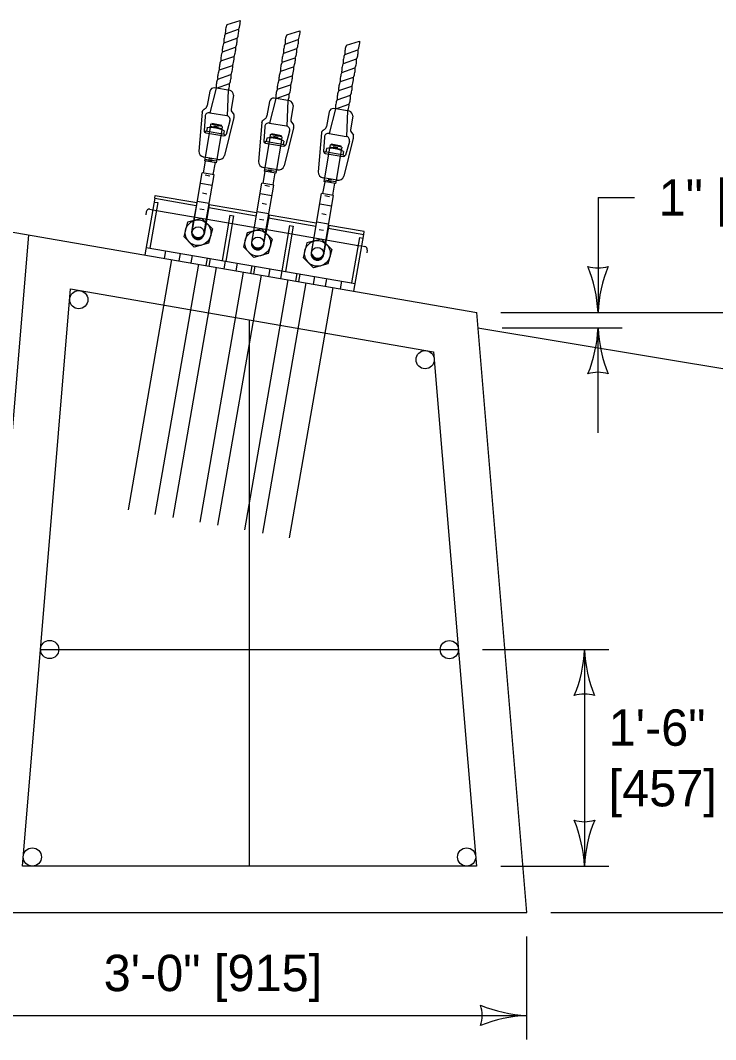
# Model space of a CAD drawing. Extents: x 49991.4 to 50021, y 49987.6 to 50011.4.
# Drawn here: x 50006.374 to 50007.521, y 49993.215 to 49994.897 of the extents above; entities that cross this region are included whole.
import ezdxf

# ---------------------------------------------------------------- set-up
doc = ezdxf.new("R2010")
doc.units = 0
for name, color, linetype in [('Level 1', 7, 'Continuous'), ('Level 2', 7, 'Continuous'), ('Level 3', 7, 'Continuous'), ('Level 4', 7, 'Continuous'), ('Level 7', 7, 'Continuous')]:
    doc.layers.add(name, color=color, linetype=linetype)

msp = doc.modelspace()

# ---------------------------------------------------------------- linework, layer by layer
at = {"layer": 'Level 1'}
for p, q in [((50006.7152, 49994.8898), (50006.7369, 49994.8968)), ((50006.7126, 49994.8749), (50006.7341, 49994.8823)), ((50006.8137, 49994.8728), (50006.8354, 49994.8798)), ((50006.7101, 49994.8599), (50006.7315, 49994.8673)), ((50006.8112, 49994.8578), (50006.8326, 49994.8652)), ((50006.9122, 49994.8557), (50006.9339, 49994.8627)), ((50006.7076, 49994.845), (50006.729, 49994.8524)), ((50006.8086, 49994.8429), (50006.83, 49994.8503)), ((50006.9097, 49994.8407), (50006.9311, 49994.8482)), ((50006.705, 49994.83), (50006.7264, 49994.8374)), ((50006.7264, 49994.8374), (50006.7264, 49994.8373)), ((50006.8061, 49994.8279), (50006.8275, 49994.8353)), ((50006.9072, 49994.8258), (50006.9286, 49994.8332)), ((50006.7025, 49994.8151), (50006.724, 49994.8225)), ((50006.8036, 49994.813), (50006.825, 49994.8204)), ((50006.825, 49994.8204), (50006.825, 49994.8203)), ((50006.9046, 49994.8108), (50006.926, 49994.8183)), ((50006.6999, 49994.8001), (50006.7215, 49994.8075)), ((50006.801, 49994.798), (50006.8225, 49994.8054)), ((50006.9021, 49994.7959), (50006.9235, 49994.8033)), ((50006.9235, 49994.8033), (50006.9235, 49994.8032)), ((50006.6864, 49994.7802), (50006.6821, 49994.7562)), ((50006.7203, 49994.7812), (50006.6941, 49994.7856)), ((50006.6974, 49994.7851), (50006.719, 49994.7926)), ((50006.6974, 49994.7852), (50006.6974, 49994.7851)), ((50006.7985, 49994.7831), (50006.82, 49994.7904)), ((50006.8996, 49994.7809), (50006.921, 49994.7883)), ((50006.7258, 49994.7735), (50006.7217, 49994.7497)), ((50006.785, 49994.7632), (50006.7807, 49994.7391)), ((50006.8188, 49994.7641), (50006.7927, 49994.7685)), ((50006.7959, 49994.768), (50006.8175, 49994.7755)), ((50006.7959, 49994.7681), (50006.7959, 49994.768)), ((50006.897, 49994.766), (50006.9186, 49994.7734)), ((50006.6741, 49994.7452), (50006.6684, 49994.681)), ((50006.7221, 49994.7477), (50006.7265, 49994.7415)), ((50006.8243, 49994.7564), (50006.8202, 49994.7326)), ((50006.8835, 49994.7461), (50006.8792, 49994.722)), ((50006.9174, 49994.747), (50006.8912, 49994.7515)), ((50006.8945, 49994.7509), (50006.916, 49994.7584)), ((50006.8945, 49994.7511), (50006.8945, 49994.7509)), ((50006.6787, 49994.7383), (50006.6772, 49994.7146)), ((50006.6865, 49994.7444), (50006.7145, 49994.7397)), ((50006.7262, 49994.7367), (50006.7107, 49994.6737)), ((50006.7198, 49994.7313), (50006.7134, 49994.7084)), ((50006.7726, 49994.7281), (50006.7669, 49994.6639)), ((50006.8206, 49994.7307), (50006.825, 49994.7244)), ((50006.9228, 49994.7394), (50006.9188, 49994.7156)), ((50006.6795, 49994.7143), (50006.6791, 49994.7115)), ((50006.7108, 49994.7087), (50006.6795, 49994.7143)), ((50006.6799, 49994.7111), (50006.7097, 49994.7061)), ((50006.682, 49994.7197), (50006.6811, 49994.714)), ((50006.6879, 49994.7255), (50006.687, 49994.7199)), ((50006.7066, 49994.7181), (50006.6873, 49994.7217)), ((50006.7072, 49994.7218), (50006.6879, 49994.7255)), ((50006.7062, 49994.7234), (50006.6899, 49994.7265)), ((50006.701, 49994.7207), (50006.6934, 49994.7221)), ((50006.7072, 49994.7218), (50006.7063, 49994.7163)), ((50006.7103, 49994.7147), (50006.7093, 49994.7089)), ((50006.7773, 49994.7212), (50006.7757, 49994.6976)), ((50006.785, 49994.7273), (50006.813, 49994.7226)), ((50006.8248, 49994.7196), (50006.8092, 49994.6567)), ((50006.8183, 49994.7142), (50006.8119, 49994.6914)), ((50006.8712, 49994.7111), (50006.8654, 49994.6469)), ((50006.9191, 49994.7136), (50006.9235, 49994.7074)), ((50006.7108, 49994.7086), (50006.7103, 49994.7061)), ((50006.7781, 49994.6972), (50006.7776, 49994.6944)), ((50006.8093, 49994.6916), (50006.7781, 49994.6972)), ((50006.7785, 49994.6941), (50006.8083, 49994.689)), ((50006.7806, 49994.7027), (50006.7796, 49994.6969)), ((50006.7864, 49994.7084), (50006.7855, 49994.7028)), ((50006.8051, 49994.701), (50006.7858, 49994.7047)), ((50006.8057, 49994.7048), (50006.7864, 49994.7084)), ((50006.8048, 49994.7064), (50006.7885, 49994.7095)), ((50006.7995, 49994.7036), (50006.7919, 49994.7051)), ((50006.8057, 49994.7048), (50006.8048, 49994.6993)), ((50006.8088, 49994.6976), (50006.8078, 49994.6919)), ((50006.8758, 49994.7041), (50006.8742, 49994.6805)), ((50006.8836, 49994.7103), (50006.9116, 49994.7055)), ((50006.9233, 49994.7025), (50006.9077, 49994.6396)), ((50006.9169, 49994.6972), (50006.9104, 49994.6743)), ((50006.8093, 49994.6916), (50006.8089, 49994.6891)), ((50006.8766, 49994.6801), (50006.8761, 49994.6774)), ((50006.9078, 49994.6745), (50006.8766, 49994.6801)), ((50006.8791, 49994.6856), (50006.8781, 49994.6799)), ((50006.885, 49994.6913), (50006.884, 49994.6858)), ((50006.9036, 49994.684), (50006.8843, 49994.6876)), ((50006.9043, 49994.6877), (50006.885, 49994.6913)), ((50006.9033, 49994.6893), (50006.887, 49994.6924)), ((50006.898, 49994.6866), (50006.8904, 49994.688)), ((50006.9043, 49994.6877), (50006.9033, 49994.6822)), ((50006.9073, 49994.6805), (50006.9064, 49994.6748)), ((50006.6791, 49994.6647), (50006.6758, 49994.645)), ((50006.6996, 49994.6673), (50006.6767, 49994.6713)), ((50006.6787, 49994.671), (50006.6776, 49994.665)), ((50006.697, 49994.662), (50006.6776, 49994.665)), ((50006.6781, 49994.6679), (50006.6975, 49994.665)), ((50006.6904, 49994.6646), (50006.6842, 49994.666)), ((50006.6909, 49994.6676), (50006.685, 49994.6686)), ((50006.6954, 49994.6622), (50006.6918, 49994.6423)), ((50006.698, 49994.6676), (50006.697, 49994.662)), ((50006.877, 49994.677), (50006.9068, 49994.672)), ((50006.9078, 49994.6745), (50006.9074, 49994.672)), ((50005.7204, 49994.6584), (50007.1271, 49994.4149)), ((50006.6606, 49994.5664), (50006.674, 49994.6453)), ((50006.6936, 49994.642), (50006.674, 49994.6453)), ((50006.7776, 49994.6477), (50006.7743, 49994.628)), ((50006.7981, 49994.6502), (50006.7752, 49994.6543)), ((50006.7772, 49994.6539), (50006.7762, 49994.6479)), ((50006.7956, 49994.6449), (50006.7762, 49994.6479)), ((50006.7767, 49994.6509), (50006.7961, 49994.6479)), ((50006.789, 49994.6476), (50006.7828, 49994.6489)), ((50006.7895, 49994.6505), (50006.7835, 49994.6516)), ((50006.794, 49994.6452), (50006.7904, 49994.6252)), ((50006.7965, 49994.6505), (50006.7956, 49994.6449)), ((50006.6906, 49994.6243), (50006.671, 49994.6276)), ((50006.6868, 49994.6399), (50006.6791, 49994.6412)), ((50006.6803, 49994.5633), (50006.6936, 49994.642)), ((50006.7591, 49994.5494), (50006.7725, 49994.6283)), ((50006.7922, 49994.6249), (50006.7725, 49994.6283)), ((50006.8762, 49994.6306), (50006.8728, 49994.6109)), ((50006.8967, 49994.6332), (50006.8737, 49994.6372)), ((50006.8757, 49994.6368), (50006.8747, 49994.6309)), ((50006.8941, 49994.6279), (50006.8747, 49994.6309)), ((50006.8752, 49994.6338), (50006.8946, 49994.6308)), ((50006.8875, 49994.6305), (50006.8813, 49994.6319)), ((50006.888, 49994.6335), (50006.8821, 49994.6345)), ((50006.8925, 49994.6281), (50006.8889, 49994.6082)), ((50006.8951, 49994.6334), (50006.8941, 49994.6279)), ((50006.6818, 49994.6101), (50006.6744, 49994.6117)), ((50006.7892, 49994.6072), (50006.7695, 49994.6105)), ((50006.7854, 49994.6228), (50006.7776, 49994.6242)), ((50006.7788, 49994.5462), (50006.7922, 49994.6249)), ((50006.8577, 49994.5323), (50006.8711, 49994.6112)), ((50006.8907, 49994.6079), (50006.8711, 49994.6112)), ((50006.5958, 49994.6034), (50006.5796, 49994.5097)), ((50006.6007, 49994.5961), (50006.5877, 49994.5212)), ((50006.5948, 49994.5971), (50006.6007, 49994.5961)), ((50006.5958, 49994.6034), (50006.5967, 49994.6081)), ((50006.5958, 49994.6034), (50006.6643, 49994.5915)), ((50006.5967, 49994.6081), (50006.6651, 49994.5963)), ((50006.6651, 49994.5963), (50006.6599, 49994.5663)), ((50006.6856, 49994.5948), (50006.666, 49994.5981)), ((50006.7803, 49994.5931), (50006.7729, 49994.5946)), ((50006.8877, 49994.5901), (50006.868, 49994.5935)), ((50006.8839, 49994.6058), (50006.8762, 49994.6071)), ((50006.8773, 49994.5291), (50006.8907, 49994.6079)), ((50006.5818, 49994.5811), (50006.581, 49994.5761)), ((50006.5876, 49994.5851), (50006.5925, 49994.5843)), ((50006.5984, 49994.5832), (50006.7177, 49994.5626)), ((50006.6771, 49994.5843), (50006.67, 49994.5855)), ((50006.6858, 49994.5927), (50006.6807, 49994.5629)), ((50006.685, 49994.588), (50006.7629, 49994.5745)), ((50006.7637, 49994.5792), (50006.6858, 49994.5927)), ((50006.7637, 49994.5792), (50006.7585, 49994.5492)), ((50006.7842, 49994.5777), (50006.7645, 49994.5811)), ((50006.8789, 49994.576), (50006.8715, 49994.5776)), ((50006.65, 49994.5636), (50006.6436, 49994.54)), ((50006.6736, 49994.5699), (50006.65, 49994.5636)), ((50006.6736, 49994.5699), (50006.6909, 49994.5526)), ((50006.7199, 49994.5754), (50006.7069, 49994.5005)), ((50006.7258, 49994.5744), (50006.7128, 49994.4995)), ((50006.7199, 49994.5754), (50006.7258, 49994.5744)), ((50006.7236, 49994.5616), (50006.8162, 49994.5455)), ((50006.7756, 49994.5672), (50006.7685, 49994.5684)), ((50006.7844, 49994.5756), (50006.7792, 49994.5458)), ((50006.7835, 49994.5709), (50006.8614, 49994.5574)), ((50006.8622, 49994.5621), (50006.7844, 49994.5756)), ((50006.8622, 49994.5621), (50006.857, 49994.5321)), ((50006.8827, 49994.5607), (50006.863, 49994.564)), ((50006.2946, 49993.4249), (50006.3877, 49994.5429)), ((50006.6909, 49994.5526), (50006.6846, 49994.529)), ((50006.7485, 49994.5465), (50006.7422, 49994.5229)), ((50006.7721, 49994.5529), (50006.7485, 49994.5465)), ((50006.7721, 49994.5529), (50006.7894, 49994.5356)), ((50006.8184, 49994.5584), (50006.8055, 49994.4835)), ((50006.8243, 49994.5573), (50006.8114, 49994.4824)), ((50006.8184, 49994.5584), (50006.8243, 49994.5573)), ((50006.8221, 49994.5445), (50006.9315, 49994.5256)), ((50006.8742, 49994.5502), (50006.867, 49994.5514)), ((50006.8829, 49994.5586), (50006.8777, 49994.5287)), ((50006.8821, 49994.5538), (50006.9407, 49994.5437)), ((50006.9415, 49994.5484), (50006.8829, 49994.5586)), ((50006.9245, 49994.45), (50006.9407, 49994.5437)), ((50006.9407, 49994.5437), (50006.9415, 49994.5484)), ((50006.6436, 49994.54), (50006.6609, 49994.5227)), ((50006.6846, 49994.529), (50006.6609, 49994.5227)), ((50006.7894, 49994.5356), (50006.7831, 49994.5119)), ((50006.847, 49994.5295), (50006.8407, 49994.5058)), ((50006.8707, 49994.5358), (50006.847, 49994.5295)), ((50006.8707, 49994.5358), (50006.888, 49994.5185)), ((50006.9337, 49994.5384), (50006.9207, 49994.4635)), ((50006.9337, 49994.5384), (50006.9396, 49994.5374)), ((50006.5818, 49994.5222), (50006.9267, 49994.4625)), ((50006.7422, 49994.5229), (50006.7595, 49994.5056)), ((50006.7831, 49994.5119), (50006.7595, 49994.5056)), ((50006.888, 49994.5185), (50006.8816, 49994.4949)), ((50006.9374, 49994.5246), (50006.9423, 49994.5237)), ((50006.9464, 49994.5179), (50006.9455, 49994.513)), ((50006.5523, 49994.0893), (50006.624, 49994.502)), ((50006.5966, 49994.0816), (50006.6683, 49994.4943)), ((50006.8407, 49994.5058), (50006.858, 49994.4885)), ((50006.8816, 49994.4949), (50006.858, 49994.4885)), ((50006.6262, 49994.0765), (50006.6979, 49994.4892)), ((50006.6705, 49994.0687), (50006.7422, 49994.4815)), ((50006.7001, 49994.0636), (50006.7718, 49994.4764)), ((50006.7444, 49994.0559), (50006.8161, 49994.4687)), ((50006.7739, 49994.0508), (50006.8457, 49994.4636)), ((50006.3774, 49993.5012), (50006.4568, 49994.4536)), ((50006.4568, 49994.4536), (50007.056, 49994.3498)), ((50006.8183, 49994.0431), (50006.89, 49994.4559)), ((50007.2096, 49993.4249), (50007.1271, 49994.4149)), ((50006.7521, 49993.5012), (50006.7521, 49994.4024)), ((50007.1292, 49994.3896), (50007.6976, 49994.2948)), ((50007.056, 49994.3498), (50007.1267, 49993.5012)), ((50006.4072, 49993.8587), (50007.0969, 49993.8587)), ((50007.1267, 49993.5012), (50006.3774, 49993.5012)), ((50006.2946, 49993.4249), (50007.2096, 49993.4249))]:
    msp.add_line(p, q, dxfattribs=at)
for centre, radius in [((50006.6673, 49994.5463), 0.0212), ((50006.6673, 49994.5463), 0.00997), ((50006.7658, 49994.5292), 0.0212), ((50006.7658, 49994.5292), 0.00997), ((50006.8643, 49994.5122), 0.0212), ((50006.8643, 49994.5122), 0.00997)]:
    msp.add_circle(centre, radius, dxfattribs=at)
for centre, radius, start, end in [((50006.6939, 49994.7777), 0.00789, 88.576, 161.4858), ((50006.717, 49994.7731), 0.00873, 2.7632, 67.9683), ((50006.7925, 49994.7607), 0.00789, 88.576, 161.4858), ((50006.8156, 49994.756), 0.00873, 2.7632, 67.9683), ((50006.6852, 49994.738), 0.00651, 78.8447, 177.8403), ((50006.7253, 49994.7493), 0.00357, 173.8219, 206.0338), ((50006.891, 49994.7436), 0.00789, 88.576, 161.4858), ((50006.9141, 49994.7389), 0.00873, 2.7632, 67.9683), ((50006.7136, 49994.7332), 0.00651, 342.7918, 82.0134), ((50006.7205, 49994.7394), 0.00638, 335.0639, 19.6741), ((50006.8238, 49994.7322), 0.00357, 173.8219, 206.0338), ((50006.681, 49994.7148), 0.00382, 182.5415, 254.2689), ((50006.6865, 49994.6637), 0.0562, 65.0322, 94.6111), ((50006.7838, 49994.721), 0.00651, 78.8447, 177.8403), ((50006.8121, 49994.7162), 0.00651, 342.7918, 82.0134), ((50006.819, 49994.7223), 0.00638, 335.0639, 19.6741), ((50006.9223, 49994.7152), 0.00357, 173.8219, 206.0338), ((50006.7098, 49994.71), 0.0039, 268.9824, 336.7399), ((50006.7795, 49994.6977), 0.00382, 182.5415, 254.2689), ((50006.7851, 49994.6467), 0.0562, 65.0322, 94.6111), ((50006.8823, 49994.7039), 0.00651, 78.8447, 177.8403), ((50006.9107, 49994.6991), 0.00651, 342.7918, 82.0134), ((50006.9175, 49994.7052), 0.00638, 335.0639, 19.6741), ((50006.6783, 49994.6812), 0.00999, 180.9854, 260.3658), ((50006.8083, 49994.6929), 0.0039, 268.9824, 336.7399), ((50006.8781, 49994.6807), 0.00382, 182.5415, 254.2689), ((50006.8836, 49994.6296), 0.0562, 65.0322, 94.6111), ((50006.7013, 49994.6771), 0.00999, 260.3658, 340.2722), ((50006.7769, 49994.6641), 0.00999, 180.9854, 260.3658), ((50006.9069, 49994.6759), 0.0039, 268.9824, 336.7399), ((50006.7998, 49994.6601), 0.00999, 260.3658, 340.2722), ((50006.8754, 49994.647), 0.00999, 180.9854, 260.3658), ((50006.8983, 49994.643), 0.00999, 260.3658, 340.2722), ((50006.5868, 49994.5802), 0.005, 80.1778, 170.1778), ((50006.9415, 49994.5188), 0.005, 350.1778, 80.1778)]:
    msp.add_arc(centre, radius, start, end, dxfattribs=at)
for centre, major_axis, ratio, start_param, end_param in [((50006.7353, 49994.8897), (-0.00127, -0.00747), 0.155406, 0, 2.845204), ((50006.7139, 49994.8823), (0.00127, 0.00747), 0.155406, 0, 3.141593), ((50006.7328, 49994.8748), (-0.00127, -0.00747), 0.155406, 0, 3.141593), ((50006.8339, 49994.8727), (-0.00127, -0.00747), 0.155406, 0, 2.845204), ((50006.7114, 49994.8674), (0.00127, 0.00747), 0.155406, 0, 3.141593), ((50006.7302, 49994.8599), (-0.00127, -0.00747), 0.155406, 0, 3.141593), ((50006.8124, 49994.8653), (0.00127, 0.00747), 0.155406, 0, 3.141593), ((50006.8313, 49994.8577), (-0.00127, -0.00747), 0.155406, 0, 3.141593), ((50006.9324, 49994.8556), (-0.00127, -0.00747), 0.155406, 0, 2.845204), ((50006.7088, 49994.8524), (0.00127, 0.00747), 0.155406, 0, 3.141593), ((50006.7277, 49994.8449), (-0.00127, -0.00747), 0.155406, 0, 3.141593), ((50006.8099, 49994.8503), (0.00127, 0.00747), 0.155406, 0, 3.141593), ((50006.8288, 49994.8428), (-0.00127, -0.00747), 0.155406, 0, 3.141593), ((50006.911, 49994.8482), (0.00127, 0.00747), 0.155406, 0, 3.141593), ((50006.9299, 49994.8407), (-0.00127, -0.00747), 0.155406, 0, 3.141593), ((50006.7038, 49994.8225), (0.00127, 0.00747), 0.155406, 0, 3.141593), ((50006.7063, 49994.8375), (0.00127, 0.00747), 0.155406, 0, 3.141593), ((50006.7251, 49994.8299), (-0.00127, -0.00747), 0.155406, 0.123954, 3.079301), ((50006.8074, 49994.8354), (0.00127, 0.00747), 0.155406, 0, 3.141593), ((50006.8262, 49994.8278), (-0.00127, -0.00747), 0.155406, 0, 3.141593), ((50006.9084, 49994.8333), (0.00127, 0.00747), 0.155406, 0, 3.141593), ((50006.9273, 49994.8257), (-0.00127, -0.00747), 0.155406, 0, 3.141593), ((50006.7012, 49994.8076), (0.00127, 0.00747), 0.155406, 0, 3.141593), ((50006.7228, 49994.815), (-0.00127, -0.00747), 0.155406, 0, 3.205419), ((50006.8023, 49994.8055), (0.00127, 0.00747), 0.155406, 0, 3.141593), ((50006.8048, 49994.8204), (0.00127, 0.00747), 0.155406, 0, 3.141593), ((50006.8236, 49994.8128), (-0.00127, -0.00747), 0.155406, 0.123954, 3.079301), ((50006.9059, 49994.8183), (0.00127, 0.00747), 0.155406, 0, 3.141593), ((50006.9248, 49994.8108), (-0.00127, -0.00747), 0.155406, 0, 3.141593), ((50006.6987, 49994.7926), (0.00127, 0.00747), 0.155406, 0, 3.141593), ((50006.7202, 49994.8), (-0.00127, -0.00747), 0.155406, 0, 3.141593), ((50006.7997, 49994.7905), (0.00127, 0.00747), 0.155406, 0, 3.141593), ((50006.8213, 49994.7979), (-0.00127, -0.00747), 0.155406, 0, 3.205419), ((50006.9008, 49994.7884), (0.00127, 0.00747), 0.155406, 0, 3.141593), ((50006.9034, 49994.8034), (0.00127, 0.00747), 0.155406, 0, 3.141593), ((50006.9222, 49994.7958), (-0.00127, -0.00747), 0.155406, 0.123954, 3.079301), ((50006.718, 49994.7871), (0.00097, 0.00547), 0.140692, 3.334186, 6.283185), ((50006.7972, 49994.7756), (0.00127, 0.00747), 0.155406, 0, 3.141593), ((50006.8188, 49994.783), (-0.00127, -0.00747), 0.155406, 0, 3.141593), ((50006.8983, 49994.7735), (0.00127, 0.00747), 0.155406, 0, 3.141593), ((50006.9198, 49994.7809), (-0.00127, -0.00747), 0.155406, 0, 3.205419), ((50006.8165, 49994.77), (0.00097, 0.00547), 0.140692, 3.334186, 6.283185), ((50006.8957, 49994.7585), (0.00127, 0.00747), 0.155406, 0, 3.141593), ((50006.9173, 49994.7659), (-0.00127, -0.00747), 0.155406, 0, 3.141593), ((50006.9151, 49994.753), (0.00097, 0.00547), 0.140692, 3.334186, 6.283185)]:
    msp.add_ellipse(centre, major_axis=major_axis, ratio=ratio, start_param=start_param, end_param=end_param, dxfattribs=at)
for points in [[(50006.6741, 49994.7452), (50006.6743, 49994.7464), (50006.6749, 49994.7478), (50006.6757, 49994.7489), (50006.677, 49994.7499), (50006.6777, 49994.7504), (50006.6791, 49994.7514), (50006.6805, 49994.7524), (50006.6814, 49994.7541), (50006.682, 49994.7555), (50006.6821, 49994.7562)], [(50006.7726, 49994.7281), (50006.7728, 49994.7293), (50006.7734, 49994.7308), (50006.7742, 49994.7319), (50006.7756, 49994.7328), (50006.7763, 49994.7333), (50006.7777, 49994.7343), (50006.7791, 49994.7353), (50006.78, 49994.737), (50006.7805, 49994.7384), (50006.7807, 49994.7391)], [(50006.8712, 49994.7111), (50006.8714, 49994.7123), (50006.8719, 49994.7137), (50006.8727, 49994.7148), (50006.8741, 49994.7158), (50006.8748, 49994.7163), (50006.8762, 49994.7173), (50006.8776, 49994.7183), (50006.8785, 49994.7199), (50006.879, 49994.7214), (50006.8792, 49994.722)]]:
    msp.add_spline(points, degree=3, dxfattribs=at)
at = {"layer": 'Level 3'}
for p, q in [((50007.3273, 49994.6044), (50007.3273, 49994.4149)), ((50007.3273, 49994.6044), (50007.3873, 49994.6044)), ((50007.1671, 49994.4149), (50007.7123, 49994.4149)), ((50007.1692, 49994.3896), (50007.3673, 49994.3896)), ((50007.3273, 49994.2161), (50007.3273, 49994.3896)), ((50007.1369, 49993.8587), (50007.3449, 49993.8587)), ((50007.3049, 49993.8587), (50007.3049, 49993.501)), ((50007.1667, 49993.501), (50007.3449, 49993.501)), ((50007.2496, 49993.4249), (50007.7123, 49993.4249)), ((50007.2096, 49993.2149), (50007.2096, 49993.3849)), ((50006.2946, 49993.2549), (50007.2096, 49993.2549))]:
    msp.add_line(p, q, dxfattribs=at)
for centre, radius, start, end in [((50007.3273, 49994.5431), 0.0548, 252.1388, 287.8612), ((50007.0946, 49994.4034), 0.233, 2.8273, 22.0772), ((50007.5495, 49994.4057), 0.2223, 157.456, 177.6395), ((50007.1052, 49994.3987), 0.2223, 337.456, 357.6395), ((50007.56, 49994.401), 0.233, 182.8273, 202.0772), ((50007.3273, 49994.2613), 0.0548, 72.1388, 107.8612), ((50007.0828, 49993.8678), 0.2223, 337.456, 357.6395), ((50007.5376, 49993.8701), 0.233, 182.8273, 202.0772), ((50007.3049, 49993.7304), 0.0548, 72.1388, 107.8612), ((50007.3049, 49993.6293), 0.0548, 252.1388, 287.8612), ((50007.0722, 49993.4895), 0.233, 2.8273, 22.0772), ((50007.5271, 49993.4919), 0.2223, 157.456, 177.6395), ((50007.2187, 49993.477), 0.2223, 247.456, 267.6395), ((50007.0813, 49993.2549), 0.0548, 342.1388, 17.8612), ((50007.221, 49993.0222), 0.233, 92.8273, 112.0772)]:
    msp.add_arc(centre, radius, start, end, dxfattribs=at)
at = {"layer": 'Level 4'}
for p, q in [((50006.6971, 49994.7851), (50006.6866, 49994.7444)), ((50006.717, 49994.7817), (50006.7153, 49994.7395)), ((50006.7956, 49994.768), (50006.7851, 49994.7273)), ((50006.8156, 49994.7647), (50006.8138, 49994.7224)), ((50006.8942, 49994.751), (50006.8837, 49994.7103)), ((50006.9141, 49994.7476), (50006.9124, 49994.7054)), ((50006.687, 49994.7199), (50006.6787, 49994.671)), ((50006.7063, 49994.7163), (50006.698, 49994.6676)), ((50006.7855, 49994.7028), (50006.7772, 49994.6539)), ((50006.8048, 49994.6993), (50006.7965, 49994.6505)), ((50006.884, 49994.6858), (50006.8757, 49994.6368)), ((50006.9033, 49994.6822), (50006.8951, 49994.6334)), ((50006.5925, 49994.5843), (50006.5984, 49994.5832)), ((50006.6567, 49994.5475), (50006.6599, 49994.5663)), ((50006.6574, 49994.548), (50006.6606, 49994.5664)), ((50006.6771, 49994.5444), (50006.6803, 49994.5633)), ((50006.6807, 49994.5629), (50006.6774, 49994.5439)), ((50006.7177, 49994.5626), (50006.7236, 49994.5616)), ((50006.7585, 49994.5492), (50006.7552, 49994.5304)), ((50006.756, 49994.5309), (50006.7591, 49994.5494)), ((50006.7756, 49994.5274), (50006.7788, 49994.5462)), ((50006.7759, 49994.5268), (50006.7792, 49994.5458)), ((50006.8162, 49994.5455), (50006.8221, 49994.5445)), ((50006.857, 49994.5321), (50006.8538, 49994.5134)), ((50006.8545, 49994.5138), (50006.8577, 49994.5323)), ((50006.8741, 49994.5103), (50006.8773, 49994.5291)), ((50006.8777, 49994.5287), (50006.8745, 49994.5098)), ((50006.6116, 49994.5041), (50006.6138, 49994.5167)), ((50006.6363, 49994.4999), (50006.6384, 49994.5124)), ((50006.656, 49994.4965), (50006.6582, 49994.509)), ((50006.9315, 49994.5256), (50006.9374, 49994.5246)), ((50006.6806, 49994.4922), (50006.6828, 49994.5047)), ((50006.6855, 49994.4913), (50006.6877, 49994.5039)), ((50006.7102, 49994.4871), (50006.7123, 49994.4996)), ((50006.7299, 49994.4837), (50006.7321, 49994.4962)), ((50006.7545, 49994.4794), (50006.7567, 49994.4919)), ((50006.7594, 49994.4786), (50006.7616, 49994.4911)), ((50006.7841, 49994.4743), (50006.7863, 49994.4868)), ((50006.8038, 49994.4709), (50006.806, 49994.4834)), ((50006.8284, 49994.4666), (50006.8306, 49994.4791)), ((50006.8333, 49994.4658), (50006.8355, 49994.4783)), ((50006.858, 49994.4615), (50006.8602, 49994.474)), ((50006.8777, 49994.4581), (50006.8799, 49994.4706)), ((50006.9023, 49994.4538), (50006.9045, 49994.4663))]:
    msp.add_line(p, q, dxfattribs=at)
for centre, radius, start, end in [((50006.667, 49994.5457), 0.0105, 170.1778, 260.1778), ((50006.6678, 49994.55), 0.0114, 192.7977, 327.5579), ((50006.667, 49994.5457), 0.0105, 260.1778, 350.1778), ((50006.7656, 49994.5286), 0.0105, 170.1778, 260.1778), ((50006.7663, 49994.5329), 0.0114, 192.7977, 327.5579), ((50006.7656, 49994.5286), 0.0105, 260.1778, 350.1778), ((50006.8641, 49994.5116), 0.0105, 170.1778, 260.1778), ((50006.8649, 49994.5159), 0.0114, 192.7977, 327.5579), ((50006.8641, 49994.5116), 0.0105, 260.1778, 350.1778)]:
    msp.add_arc(centre, radius, start, end, dxfattribs=at)
at = {"layer": 'Level 7'}
for centre in [(50006.4704, 49994.436), (50007.042, 49994.337), (50006.4223, 49993.8587), (50007.0819, 49993.8584), (50006.3937, 49993.5162), (50007.1104, 49993.5162)]:
    msp.add_circle(centre, 0.015, dxfattribs=at)

# ---------------------------------------------------------------- texts
at = {"layer": 'Level 2'}
for s, p in [('1" [25]', (50007.4273, 49994.5744)), ('1\'-6"', (50007.3449, 49993.6998)), ('[457]', (50007.3449, 49993.5998)), ('3\'-0" [915]', (50006.5115, 49993.2949))]:
    msp.add_text(s, height=0.06, dxfattribs=at).set_placement(p)

doc.saveas('drawing.dxf')
